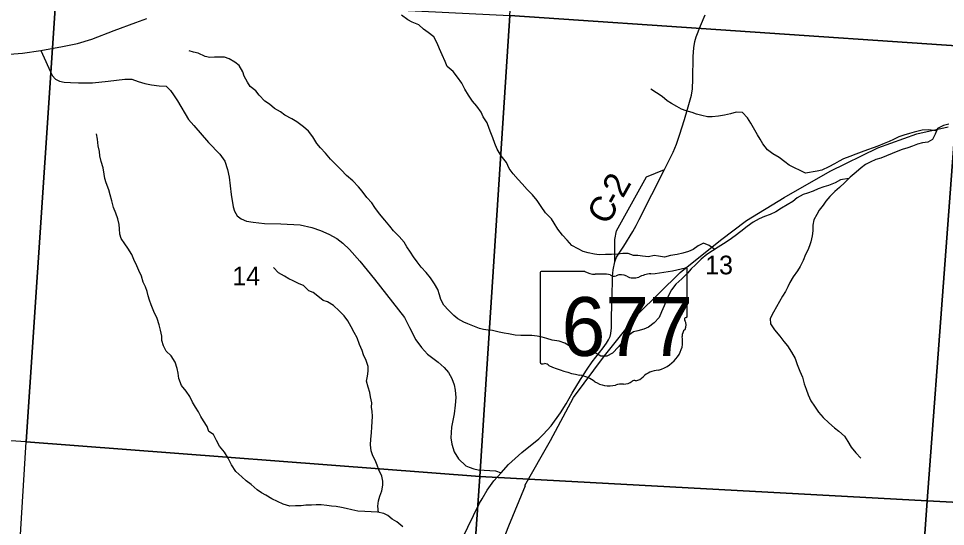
# Model space of a CAD drawing. Extents: x 0 to 34, y 0 to 22.
# Drawn here: x 24.565 to 26.642, y 15.854 to 16.992 of the extents above; entities that cross this region are included whole.
import ezdxf

# ---------------------------------------------------------------- set-up
doc = ezdxf.new("R2010")
doc.units = 0
for name, color, linetype in [('GM_X_County_Road', 7, 'Continuous'), ('GM_X_County_Road_Text', 7, 'Continuous'), ('GM_X_Minor_River', 7, 'Continuous'), ('GM_X_Rail_Line', 7, 'Continuous'), ('GM_X_Section', 7, 'Continuous'), ('GM_X_Section_Text', 7, 'Continuous'), ('GM_X_State_Location', 7, 'Continuous'), ('GM_X_State_Route', 7, 'Continuous'), ('GM_X_State_Shield', 7, 'Continuous'), ('GM_X_Township_Road', 7, 'Continuous')]:
    doc.layers.add(name, color=color, linetype=linetype)

msp = doc.modelspace()

# ---------------------------------------------------------------- linework, layer by layer
at = {"layer": 'GM_X_County_Road'}
msp.add_lwpolyline([(25.9013, 16.4469), (25.9018, 16.4969), (25.9051, 16.5157), (25.9727, 16.6371), (26.0131, 16.6537)], dxfattribs=at)
at = {"layer": 'GM_X_Minor_River'}
for points in [[(26.1256, 16.4744), (26.1131, 16.4832), (26.1002, 16.4881), (26.0881, 16.4824), (26.0768, 16.4744), (26.0666, 16.4694), (26.0541, 16.466), (26.0413, 16.4633), (26.0265, 16.4606), (26.0129, 16.4568), (25.9996, 16.459), (25.9894, 16.4605), (25.9769, 16.4578), (25.9637, 16.4593), (25.9534, 16.4604), (25.9436, 16.4604), (25.9315, 16.4649), (25.9197, 16.4649), (25.908, 16.4637), (25.894, 16.4633), (25.8808, 16.4629), (25.8664, 16.4625), (25.8561, 16.464), (25.8421, 16.4666), (25.8304, 16.47), (25.8194, 16.4756), (25.8054, 16.4832), (25.7951, 16.4949), (25.7841, 16.5059), (25.7738, 16.5195), (25.7655, 16.5328), (25.7594, 16.5426), (25.7461, 16.5562), (25.7366, 16.5702), (25.7278, 16.5839), (25.7172, 16.5967), (25.7054, 16.6088), (25.694, 16.6209), (25.6853, 16.6308), (25.6739, 16.6433), (25.6651, 16.6554), (25.6586, 16.669), (25.6465, 16.6838), (25.6381, 16.6989), (25.6324, 16.7114), (25.6278, 16.7243), (25.6236, 16.7353), (25.6202, 16.7455), (25.6152, 16.758), (25.6064, 16.7716), (25.6019, 16.7819), (25.592, 16.7955), (25.5829, 16.8068), (25.5734, 16.8197), (25.5654, 16.833), (25.5589, 16.847), (25.549, 16.8602), (25.5395, 16.8731), (25.5262, 16.8841), (25.5212, 16.895), (25.5148, 16.9106), (25.5083, 16.9238), (25.5033, 16.9367), (25.4961, 16.9503), (25.4832, 16.9606), (25.4726, 16.9674), (25.4623, 16.9772), (25.4471, 16.9836), (25.4377, 16.9885), (25.4236, 16.9991)], [(25.3147, 16.628), (25.3002, 16.6397), (25.2885, 16.6529), (25.2763, 16.6646), (25.2645, 16.6768), (25.2531, 16.69), (25.2418, 16.7017), (25.2338, 16.7116), (25.2246, 16.7267), (25.2151, 16.7392), (25.2037, 16.7487), (25.1889, 16.7604), (25.1779, 16.7672), (25.1624, 16.7751), (25.1522, 16.7823), (25.1393, 16.7898), (25.1275, 16.8), (25.1176, 16.8065), (25.1047, 16.8197), (25.0971, 16.8295), (25.0846, 16.8394), (25.0781, 16.8492), (25.0713, 16.8628), (25.0678, 16.8723), (25.0598, 16.8867), (25.0503, 16.8939), (25.0374, 16.9014), (25.0268, 16.9052), (25.0151, 16.9048), (25.0045, 16.9048), (24.9943, 16.9044), (24.9833, 16.9062), (24.9678, 16.9138), (24.9575, 16.9164), (24.9481, 16.919)], [(26.6221, 16.7398), (26.6044, 16.7422), (26.5904, 16.7414), (26.5722, 16.7372), (26.5616, 16.7342), (26.5491, 16.7303), (26.5382, 16.7269), (26.5261, 16.7208), (26.5159, 16.7162), (26.5053, 16.7117), (26.4906, 16.7056), (26.4803, 16.7017), (26.4675, 16.6972), (26.4535, 16.6922), (26.4418, 16.6876), (26.4278, 16.6826), (26.4142, 16.6769), (26.404, 16.672), (26.3938, 16.6659), (26.3813, 16.6594), (26.3651, 16.6522), (26.3552, 16.6495), (26.3287, 16.6449), (26.3155, 16.652), (26.3056, 16.6562), (26.2923, 16.663), (26.2825, 16.6702), (26.2696, 16.68), (26.2552, 16.6883), (26.2438, 16.6977), (26.2335, 16.7106), (26.227, 16.7212), (26.221, 16.7314), (26.2122, 16.747), (26.2065, 16.7572), (26.1989, 16.7693), (26.1875, 16.7814), (26.1731, 16.7818), (26.1606, 16.7783), (26.147, 16.7749), (26.1338, 16.7729), (26.1198, 16.7714), (26.1095, 16.7714), (26.0963, 16.774), (26.0845, 16.7777), (26.0751, 16.7811), (26.061, 16.7849), (26.0508, 16.7883), (26.0402, 16.7943), (26.0284, 16.8015), (26.0189, 16.8075), (26.0079, 16.817), (25.995, 16.8249), (25.9821, 16.8336)], [(26.6501, 16.7549), (26.6377, 16.7518), (26.6244, 16.7453), (26.6192, 16.7328), (26.6135, 16.7206), (26.6026, 16.7149), (26.5912, 16.713), (26.5795, 16.7099), (26.5682, 16.7057), (26.5579, 16.7019), (26.5455, 16.6985), (26.5356, 16.6943), (26.5232, 16.6889), (26.5099, 16.684), (26.4975, 16.679), (26.4865, 16.6756), (26.4736, 16.6699), (26.4631, 16.6645), (26.4532, 16.6573), (26.4423, 16.6474), (26.4291, 16.636), (26.4166, 16.6242), (26.4049, 16.6132), (26.3944, 16.6041), (26.383, 16.593), (26.3744, 16.5828), (26.3683, 16.5733), (26.3597, 16.5623), (26.3544, 16.5528), (26.3476, 16.5403), (26.3454, 16.5285), (26.3451, 16.516), (26.3436, 16.5046), (26.341, 16.4917), (26.338, 16.4822), (26.3342, 16.4727), (26.329, 16.4628), (26.3233, 16.4492), (26.3169, 16.4359), (26.3109, 16.426), (26.3015, 16.4127), (26.2936, 16.4006), (26.2891, 16.3903), (26.2838, 16.3804), (26.277, 16.3698), (26.2706, 16.358), (26.2638, 16.3459), (26.2571, 16.3334), (26.2495, 16.3197), (26.25, 16.3076), (26.2591, 16.2943), (26.2709, 16.2803), (26.28, 16.2678), (26.2887, 16.258), (26.2975, 16.244), (26.3055, 16.23), (26.3104, 16.2167), (26.3158, 16.2019), (26.3219, 16.1879), (26.3261, 16.1735), (26.3299, 16.161), (26.3349, 16.1485), (26.3406, 16.1352), (26.3486, 16.1231), (26.3581, 16.1099), (26.368, 16.0978), (26.3813, 16.0857), (26.3938, 16.0747), (26.4033, 16.0671), (26.4158, 16.0558), (26.4234, 16.0437), (26.431, 16.0312), (26.4413, 16.0187), (26.4527, 16.007)], [(24.835, 16.4269), (24.8308, 16.4379), (24.8239, 16.4519), (24.8193, 16.4633), (24.8106, 16.4769), (24.8037, 16.4868), (24.7953, 16.4989), (24.7927, 16.5087), (24.7919, 16.5205), (24.7911, 16.53), (24.7876, 16.5425), (24.7834, 16.5557), (24.7781, 16.5682), (24.7746, 16.583), (24.7704, 16.5963), (24.7681, 16.608), (24.762, 16.6236), (24.759, 16.633), (24.7574, 16.6429), (24.7547, 16.6573), (24.7505, 16.6713), (24.7478, 16.6838), (24.7466, 16.6937), (24.7439, 16.7066), (24.742, 16.7214), (24.7401, 16.7335)], [(26.4259, 16.633), (26.4075, 16.6299), (26.3954, 16.6238), (26.3803, 16.6177), (26.3701, 16.6146), (26.3572, 16.6097), (26.3459, 16.6047), (26.3334, 16.6005), (26.3236, 16.5971), (26.3104, 16.5902), (26.3002, 16.5818), (26.2877, 16.5739), (26.2752, 16.567), (26.262, 16.5582), (26.2495, 16.5529), (26.2371, 16.5479), (26.2246, 16.5426), (26.2114, 16.5354), (26.1982, 16.5259), (26.1838, 16.5148), (26.171, 16.5045), (26.1577, 16.4954), (26.1449, 16.487), (26.1328, 16.4794), (26.1207, 16.4711), (26.1079, 16.4627), (26.095, 16.4528), (26.0826, 16.4399), (26.0724, 16.4307), (26.0641, 16.4209), (26.0517, 16.4083), (26.0381, 16.3962), (26.0286, 16.3836), (26.023, 16.3741), (26.017, 16.3616), (26.0121, 16.3476), (26.0061, 16.3346), (26.0005, 16.3221), (25.9895, 16.31), (25.9767, 16.3004), (25.9665, 16.2955), (25.9529, 16.2917), (25.943, 16.2897), (25.9302, 16.2799), (25.9196, 16.2684), (25.9094, 16.2559), (25.8962, 16.2422), (25.8838, 16.235), (25.8701, 16.2353), (25.8576, 16.2429), (25.8478, 16.2429), (25.8379, 16.2417), (25.8251, 16.2451), (25.8156, 16.2481), (25.8027, 16.2564), (25.7894, 16.2643), (25.7769, 16.2685), (25.7614, 16.2711), (25.7493, 16.2749), (25.7386, 16.2775), (25.7273, 16.2797), (25.7152, 16.2812), (25.7012, 16.2812), (25.6906, 16.2815), (25.6781, 16.2823), (25.6633, 16.2849), (25.6534, 16.2864), (25.6425, 16.2886), (25.6277, 16.2924), (25.6178, 16.2935), (25.6076, 16.295), (25.5981, 16.2969), (25.5724, 16.3074), (25.5629, 16.3112), (25.55, 16.3191), (25.5405, 16.3263), (25.5291, 16.338), (25.5185, 16.3494), (25.5116, 16.3619), (25.5086, 16.3725), (25.5047, 16.3846), (25.4975, 16.3975), (25.4888, 16.4107), (25.4785, 16.4225), (25.4675, 16.4346), (25.4587, 16.4463), (25.4507, 16.458), (25.4435, 16.4679), (25.4355, 16.4804), (25.4294, 16.4906), (25.4184, 16.5035), (25.4055, 16.5163), (25.3971, 16.5262), (25.3865, 16.5398), (25.3743, 16.5542), (25.3641, 16.5685), (25.3572, 16.5784), (25.3462, 16.5909), (25.3352, 16.6049), (25.3268, 16.6147), (25.3147, 16.628)], [(25.3718, 15.8852), (25.3708, 15.8993), (25.3723, 15.9114), (25.3753, 15.9213), (25.3794, 15.9334), (25.3816, 15.9459), (25.382, 15.9554), (25.3793, 15.9664), (25.3724, 15.9804), (25.369, 15.9907), (25.3648, 16.0024), (25.3591, 16.0122), (25.3552, 16.0232), (25.3537, 16.0365), (25.3548, 16.0494), (25.3566, 16.0634), (25.3573, 16.0771), (25.3577, 16.0881), (25.3584, 16.1006), (25.3576, 16.1116), (25.3561, 16.1211), (25.3568, 16.1309), (25.3541, 16.1442), (25.3529, 16.1537), (25.3487, 16.1658), (25.3453, 16.1794), (25.3471, 16.1901), (25.349, 16.2014), (25.349, 16.2121), (25.3444, 16.2253), (25.3387, 16.2382), (25.3352, 16.2481), (25.3295, 16.2613), (25.3245, 16.2761), (25.3177, 16.2882), (25.3108, 16.3011), (25.3032, 16.314), (25.2948, 16.3257), (25.2838, 16.3367), (25.2709, 16.3484), (25.2576, 16.3571), (25.2478, 16.3597), (25.236, 16.3699), (25.2254, 16.3775), (25.2159, 16.3812), (25.2038, 16.3937), (25.1939, 16.3971), (25.181, 16.4043), (25.1712, 16.4088), (25.1617, 16.4145), (25.1476, 16.422), (25.1366, 16.4341)], [(25.4262, 15.8531), (25.4129, 15.8641), (25.4027, 15.8702), (25.3932, 15.8781), (25.3837, 15.883), (25.3697, 15.8856), (25.3417, 15.8871), (25.3254, 15.8882), (25.3121, 15.8908), (25.2996, 15.8942), (25.2894, 15.8964), (25.2769, 15.8983), (25.2663, 15.8994), (25.2561, 15.9009), (25.2432, 15.902), (25.2322, 15.902), (25.2216, 15.9016), (25.2088, 15.9011), (25.1989, 15.9), (25.1861, 15.8996), (25.1732, 15.8995), (25.1584, 15.9037), (25.1455, 15.9097), (25.133, 15.9154), (25.1194, 15.9241), (25.1099, 15.9293), (25.1, 15.9361), (25.0867, 15.9475), (25.0757, 15.9558), (25.0659, 15.9649), (25.0522, 15.977), (25.0423, 15.9921), (25.0354, 16.0065), (25.0271, 16.0202), (25.016, 16.0338), (25.0088, 16.0463), (25.0019, 16.0595), (24.9921, 16.0667), (24.9879, 16.0777), (24.9799, 16.0906), (24.9738, 16.1004), (24.9685, 16.1106), (24.9616, 16.1212), (24.9555, 16.1318), (24.9491, 16.1447), (24.9407, 16.1568), (24.9304, 16.1697), (24.9243, 16.1849), (24.9228, 16.1974), (24.9208, 16.2076), (24.9166, 16.2216), (24.9071, 16.236), (24.8965, 16.2462), (24.8904, 16.2587), (24.8866, 16.2701), (24.8862, 16.2799), (24.8835, 16.2936), (24.8808, 16.3057), (24.8758, 16.3194), (24.8682, 16.3349), (24.8628, 16.35), (24.8586, 16.3606), (24.856, 16.3701), (24.8533, 16.3803), (24.8498, 16.3902), (24.8449, 16.4012), (24.8407, 16.4141), (24.835, 16.4269)]]:
    msp.add_lwpolyline(points, dxfattribs=at)
at = {"layer": 'GM_X_Rail_Line'}
for points in [[(25.6998, 15.9455), (25.7575, 16.0461), (25.8092, 16.1428), (25.8784, 16.2363), (25.9531, 16.3294), (26.0479, 16.4228), (26.1383, 16.4948), (26.1964, 16.5392), (26.2811, 16.5903), (26.3842, 16.6494), (26.4907, 16.7016), (26.5786, 16.733), (26.6481, 16.7486)], [(25.6278, 15.7636), (25.6638, 15.8551), (25.7013, 15.9453)]]:
    msp.add_lwpolyline(points, dxfattribs=at)
at = {"layer": 'GM_X_Section'}
for points in [[(25.7287, 17.9991), (26.7513, 17.9427), (26.6773, 16.93), (25.6662, 16.9982)], [(24.6497, 17.049), (24.5822, 16.0431), (23.5665, 16.1079), (23.6339, 17.1388)], [(24.6497, 17.049), (25.6662, 16.9982), (25.5991, 15.9654), (24.5822, 16.0431)], [(25.6662, 16.9982), (26.6773, 16.93), (26.6015, 15.9112), (25.5991, 15.9654)], [(27.6556, 16.8655), (27.6283, 16.4618), (27.6018, 16.0551), (27.5892, 15.8592), (26.6015, 15.9112), (26.6773, 16.93)], [(25.5991, 15.9654), (25.5272, 14.9411), (24.518, 15.0047), (24.5822, 16.0431)], [(26.6015, 15.9112), (26.5271, 14.8668), (25.5272, 14.9411), (25.5991, 15.9654)], [(26.6015, 15.9112), (27.5892, 15.8592), (27.5781, 15.6831), (27.5261, 14.8062), (26.5271, 14.8668)]]:
    msp.add_lwpolyline(points, close=True, dxfattribs=at)
at = {"layer": 'GM_X_State_Route'}
for points in [[(25.8063, 16.152), (25.8244, 16.1833), (25.8392, 16.2061), (25.8508, 16.2228), (25.8752, 16.2536), (25.883, 16.2643), (25.8875, 16.2718), (25.8911, 16.2793), (25.8927, 16.286), (25.8941, 16.299), (25.8943, 16.3265), (25.8955, 16.3644), (25.8966, 16.4134), (25.8976, 16.4289), (25.9013, 16.4469), (25.9054, 16.4568), (25.9214, 16.4818), (25.9419, 16.5147), (25.9491, 16.5277), (25.9564, 16.5416), (26.0131, 16.6537), (26.0204, 16.6681), (26.0321, 16.6921), (26.0399, 16.7099), (26.0467, 16.7302), (26.0576, 16.7653), (26.0645, 16.7883), (26.0731, 16.8196), (26.0754, 16.8341), (26.0763, 16.8558), (26.0773, 16.9067), (26.0788, 16.9261), (26.0806, 16.9398), (26.0838, 16.9505), (26.0934, 16.9755), (26.1042, 17.0002)], [(25.5585, 15.8248), (25.5986, 15.9056), (25.6041, 15.9156), (25.6155, 15.9348), (25.6303, 15.956), (25.6465, 15.9741), (25.6633, 15.9923), (25.6935, 16.0191), (25.7311, 16.05), (25.7411, 16.0597), (25.7591, 16.0793), (25.7796, 16.1081), (25.7927, 16.1286), (25.8063, 16.152)]]:
    msp.add_lwpolyline(points, dxfattribs=at)
at = {"layer": 'GM_X_State_Shield'}
for p, q in [((26.0639, 16.3254), (26.0639, 16.4301)), ((25.7343, 16.4217), (25.7343, 16.2215)), ((25.8341, 16.4251), (25.7376, 16.4251)), ((26.0639, 16.3254), (26.0639, 16.3254))]:
    msp.add_line(p, q, dxfattribs=at)
for centre, major_axis, start_param, end_param in [((25.9465, 16.6979), (0.3495, 0), 4.814394, 5.042369), ((26.0603, 16.4305), (0.00367, 0), 6.141152, 7.989035), ((25.7381, 16.4221), (0.00382, 0), 1.712693, 3.28349), ((25.8571, 16.4483), (0.037, 0), 4.042523, 4.731795), ((25.8694, 16.3128), (0.133, 0), 1.404758, 1.657858), ((25.8996, 16.4231), (0.0107, 0), 3.836095, 5.185415), ((25.9152, 16.4), (0.0222, 0), 0.950623, 2.079405), ((25.9439, 16.4317), (0.0267, 0), 4.081561, 5.145723), ((25.9911, 16.364), (0.0703, 0), 1.699011, 2.107814), ((26.06, 16.325), (0.00393, 0), 5.05454, 6.418171), ((26.0631, 16.3177), (0.00568, 0), 1.883978, 3.671073), ((26.027, 16.3045), (0.0341, 0), 5.934695, 6.695948), ((26.0771, 16.2816), (0.0248, 0), 2.387724, 3.262537), ((25.9661, 16.2683), (0.0874, 0), 5.101752, 6.440018), ((25.7382, 16.2211), (0.00385, 0), 3.00124, 4.508301), ((25.7387, 16.2416), (0.0294, 0), 4.665946, 4.897461), ((25.7448, 16.21), (0.0106, 0), 0.519207, 1.627899), ((25.8786, 16.3898), (0.2524, 0), 4.195997, 4.488961), ((26.003, 16.1654), (0.0479, 0), 1.647645, 2.488434), ((25.8033, 16.1316), (0.079, 0), 0.823519, 1.323587), ((25.9455, 16.1746), (0.00752, 0), 1.147584, 2.315152), ((25.9423, 16.2022), (0.0282, 0), 4.937069, 5.64225), ((25.8887, 16.209), (0.0501, 0), 4.026481, 4.996735), ((25.9177, 16.1398), (0.0412, 0), 1.495662, 1.94098), ((25.9214, 16.194), (0.0267, 0), 4.691044, 5.507374)]:
    msp.add_ellipse(centre, major_axis=major_axis, ratio=0.8, start_param=start_param, end_param=end_param, dxfattribs=at)
at = {"layer": 'GM_X_Township_Road'}
for points in [[(24.1366, 16.8734), (24.1444, 16.8754), (24.1681, 16.8798), (24.2036, 16.8832), (24.244, 16.8868), (24.2751, 16.8889), (24.3013, 16.8907), (24.3206, 16.8903), (24.3459, 16.8896), (24.369, 16.89), (24.3931, 16.891), (24.4105, 16.8939), (24.4483, 16.8989), (24.4664, 16.9016), (24.5257, 16.9105), (24.5742, 16.9142), (24.6152, 16.9196), (24.6642, 16.929), (24.6972, 16.9354), (24.7297, 16.9455), (24.7799, 16.965), (24.8281, 16.9828), (24.8527, 16.9918)], [(24.6152, 16.9196), (24.6405, 16.8642), (24.6486, 16.8554), (24.657, 16.8509), (24.6677, 16.8493), (24.6819, 16.848), (24.6998, 16.8473), (24.7308, 16.8477), (24.7661, 16.8515), (24.7849, 16.8535), (24.8037, 16.8558), (24.8193, 16.8554), (24.8332, 16.8506), (24.8484, 16.8457), (24.8636, 16.8428), (24.8808, 16.8405), (24.8963, 16.8399), (24.9061, 16.8305), (24.9129, 16.8208), (24.9219, 16.8075), (24.9459, 16.7651), (24.9582, 16.7518), (24.9909, 16.7135), (25.0165, 16.6877), (25.0278, 16.6718), (25.034, 16.6537), (25.0372, 16.6362), (25.0418, 16.597), (25.046, 16.5701), (25.0495, 16.5597), (25.0554, 16.5494), (25.0644, 16.5432), (25.0764, 16.538), (25.0915, 16.5356), (25.1166, 16.5322), (25.1535, 16.5316), (25.1962, 16.5296), (25.2228, 16.5238), (25.2422, 16.5167), (25.261, 16.5082), (25.2785, 16.4985), (25.2921, 16.4885), (25.307, 16.4739), (25.3303, 16.448), (25.3627, 16.4078), (25.4304, 16.3217), (25.4417, 16.2997), (25.456, 16.2721), (25.4683, 16.2547), (25.4819, 16.2398), (25.5056, 16.2218), (25.5188, 16.21), (25.5289, 16.1986), (25.5366, 16.1853), (25.5415, 16.1708), (25.5441, 16.1591), (25.5453, 16.1428), (25.5441, 16.1254), (25.5419, 16.1059), (25.5353, 16.0762), (25.5344, 16.0526), (25.5366, 16.0383), (25.5415, 16.0212), (25.5509, 16.0053), (25.5676, 15.9898), (25.5748, 15.9862), (25.5858, 15.9828), (25.5954, 15.9804), (25.6084, 15.9796), (25.6214, 15.9792), (25.6341, 15.9785), (25.6465, 15.9741)]]:
    msp.add_lwpolyline(points, dxfattribs=at)

# ---------------------------------------------------------------- texts
at = {"layer": 'GM_X_County_Road_Text'}
for s, rotation, p in [('2', 60.6644, (25.9195, 16.5871)), ('-', 60.9088, (25.9083, 16.567)), ('C', 60.9088, (25.8858, 16.5265))]:
    msp.add_text(s, height=0.0568, rotation=rotation, dxfattribs=at).set_placement(p)
at = {"layer": 'GM_X_Section_Text'}
for s, p in [('13', (26.104, 16.4185)), ('14', (25.0444, 16.3938))]:
    msp.add_text(s, height=0.04186, rotation=0, dxfattribs=at).set_placement(p)
at = {"layer": 'GM_X_State_Location'}
for s in ['r', 's']:
    msp.add_text(s, height=0.000189, dxfattribs=at).set_placement((25.8954, 16.3083))
msp.add_text('677', height=0.000189, rotation=0, dxfattribs=at).set_placement((25.8286, 16.2945))
at = {"layer": 'GM_X_State_Shield'}
msp.add_text('677', height=0.13184, dxfattribs=at).set_placement((25.7822, 16.2357))

doc.saveas('drawing.dxf')
